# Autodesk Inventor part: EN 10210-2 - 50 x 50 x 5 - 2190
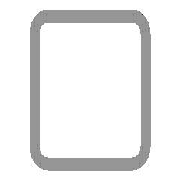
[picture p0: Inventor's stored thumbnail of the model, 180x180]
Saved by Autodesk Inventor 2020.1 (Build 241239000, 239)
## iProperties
IsCustomPart: 1
Created: 2019-01
Part Number: EN 10210-2 - 50 x 50 x 5 - 2190
Material: Stahl, weich
Description: Rohrleitung
Document SubType Name: Modeling
Standard: DIN
Designer: lutzd
Standard Revision: 2006-07
Standards Organization: DIN
Language: de-DE
Size Designation: 50 x 50 x 5
Categories: <MemberInstance><Categories><Category DisplayName="Profile" InternalName="089c4875-fa83-4c05-b084-43b9cc11f5ed" Mnemonic="GRDR"><CategoryParameter DisplayName="
Stock Number: 50 x 50 x 5
Mass: 15011.2 g
Surface Area: 7431.49 cm^2
Volume: 1912.25 cm^3
Density: 7.85 g/cm^3
Appearance: Halbpoliert
G_W: 50,000 mm
G_H: 50,000 mm
DocNumber: ADSK-014215
Folder: .
Dimensions: 50x50x2190 mm
Mass: 15,011 kg
+FF4732F2-777A-4ECC-80C5-DE08C4274734+SCHNITTDETAIL2: Schnittwinkel 90,00 grd
G_L: 2190,000 mm
_CCFamilyMember: 16
_CCFamilyDisplayName: DIN EN 10210-2 (USAS B17.1 quadratisch) - Rohrleitung — In Klammern angegebene Größen wurden aufgehoben
_FrameMemberDoc: Frame Member File
_Version: 15.0.0
_GetPNFromCC: 1
Title: Profil-Bauteil
Author: lutzd
Revision Number: -
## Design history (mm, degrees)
node "Startebene"
node "Endebene"
sketch "Skizze"
  geometry: L1 (-25, -17.5)-(-25, 17.5); L2 (-17.5, 25)-(17.5, 25); L3 (25, 17.5)-(25, -17.5); L4 (17.5, -25)-(-17.5, -25); L5 (-15, 20)-(15, 20); L6 (20, 15)-(20, -15); L7 (15, -20)-(-15, -20); L8 (-20, -15)-(-20, 15); L9 (0, 37.175)-(0, -37.175) reference; L10 (-37.175, 0)-(37.175, 0) reference; A1 r 7.5 centre (-17.5, -17.5) between (-25, -17.5) and (-17.5, -25); A2 r 7.5 centre (-17.5, 17.5) between (-17.5, 25) and (-25, 17.5); A3 r 7.5 centre (17.5, 17.5) between (25, 17.5) and (17.5, 25); A4 r 7.5 centre (17.5, -17.5) between (17.5, -25) and (25, -17.5); A5 r 5 centre (-15, -15) between (-20, -15) and (-15, -20); A6 r 5 centre (-15, 15) between (-15, 20) and (-20, 15); A7 r 5 centre (15, 15) between (20, 15) and (15, 20); A8 r 5 centre (15, -15) between (15, -20) and (20, -15)
  constraints: 16 end point, 16 point on circle, 16 tangent, 8 centre point, 6 equal radius, 4 parallel, 2 perpendicular, 2 other
  dimensions: "d7" = 7.5 radius of A1 (= G_IR); "d10" = 50 distance between parallel lines of L2 L4 (= G_H); "d11" = 50 distance between parallel lines of L1 L3 (= G_W); "d12" = 5 distance between parallel lines of L3 L6 (= G_T); "d15" = 25 distance between parallel lines of L2 L10 (= 0.5 x d10); "d16" = 25 distance between parallel lines of L9 L3 (= 0.5 x d11); "d19" = 5 radius of A5 (= G_T); "d20" = 5 distance between parallel lines of L4 L7 (= G_T)
extrude "Körper" new body sketch "Skizze" stored distance "d3" = 2190 (= G_L); taper "d4" = 0 deg
node "Driven Length"
  sketch "Sketch3"
    geometry: L1 (0, 0)-(10, 0) reference
    constraints: 2 end point, 1 horizontal
  workplane "Work Plane3"
  sketch "Sketch4"
    geometry: L1 (-2, 35)-(12, 35) reference; L2 (-2, 2225)-(12, 2225) reference
    dimensions: "d18" = 2190 distance between parallel lines of L1 L2 (derived)
workplane "Arbeitsebene5"
feature "Trennen2"
body "Solid1"
other parameters: "G_W" = 50 [user parameter; used in 1 equation term], "G_H" = 50 [user parameter; used in 1 equation term], "G_T" = 5 [user parameter; used in 3 equation terms], "G_IR" = 7.5 [user parameter; used in 1 equation term], "G_L" = 2190 (= d18) [user parameter; used in 1 equation term], "G_OFFSET_START" = -35 [user parameter; used in 1 equation term], "G_OFFSET_END" = 0 [user parameter; used in 1 equation term], "d13" = 35 (= -G_OFFSET_START), "d14" = 2225 (= G_OFFSET_END + B_L), "B_L" = 2225 [user parameter; used in 1 equation term], "d17" = 90 deg
